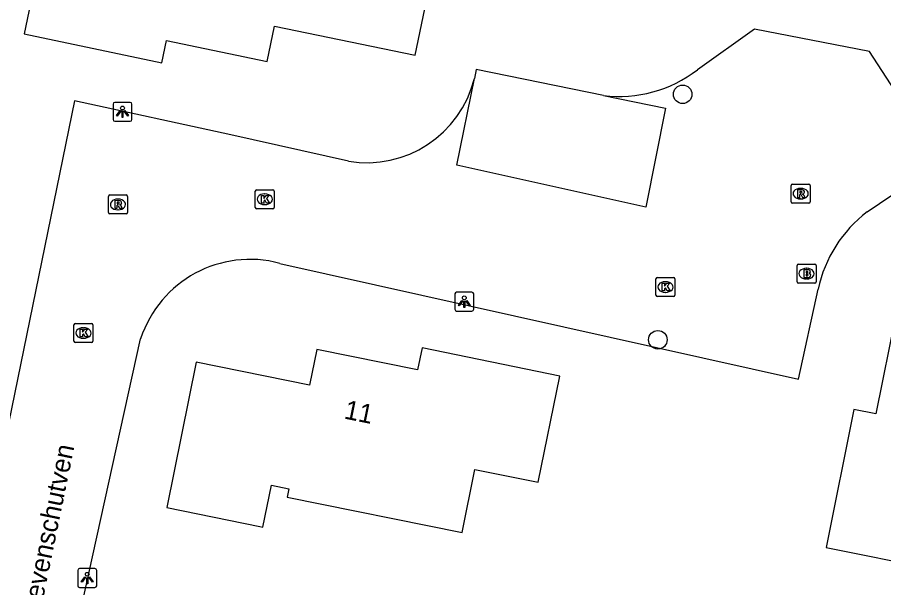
# Model space of a CAD drawing. Extents: x 163427 to 164190, y 380331 to 381641.
# Drawn here: x 163640.94 to 163686.54, y 381532.46 to 381562.48 of the extents above; entities that cross this region are included whole.
import ezdxf

# ---------------------------------------------------------------- set-up
doc = ezdxf.new("R2010")
doc.units = 0
for name, color, linetype in [('IMGEO_Boom', 7, 'Continuous'), ('IMGEO_Brandkraan', 7, 'Continuous'), ('IMGEO_Kolk', 7, 'Continuous'), ('IMGEO_Lichtpunt', 7, 'Continuous'), ('IMGEO_Openbare_ruimte_label', 7, 'Continuous'), ('IMGEO_Pand', 7, 'Continuous'), ('IMGEO_Pand_nummerreeks', 7, 'Continuous'), ('IMGEO_Parkeervlak_open', 7, 'Continuous'), ('IMGEO_Rijbaan_lokaal_open', 7, 'Continuous'), ('IMGEO_Rioolput', 7, 'Continuous')]:
    doc.layers.add(name, color=color, linetype=linetype)

msp = doc.modelspace()

# ---------------------------------------------------------------- linework, layer by layer
at = {"layer": 'IMGEO_Boom'}
for centre in [(163675.966, 381558.43), (163674.659, 381545.509)]:
    msp.add_circle(centre, 0.489, dxfattribs=at)
at = {"layer": 'IMGEO_Brandkraan'}
for p, q in [((163681.986, 381548.564), (163681.986, 381549.416)), ((163682.061, 381549.49), (163682.913, 381549.49)), ((163682.474, 381549.27), (163682.499, 381549.27)), ((163682.987, 381549.416), (163682.987, 381548.564)), ((163682.497, 381548.71), (163682.472, 381548.71)), ((163682.913, 381548.49), (163682.061, 381548.49))]:
    msp.add_line(p, q, dxfattribs=at)
for points in [[(163681.986, 381548.564), (163681.986, 381549.416)], [(163682.061, 381549.49), (163682.913, 381549.49)], [(163682.334, 381549.19), (163682.334, 381548.79), (163682.547, 381548.79)], [(163682.565, 381549.19), (163682.334, 381549.19)], [(163682.513, 381549.109), (163682.459, 381549.109), (163682.459, 381549.033)], [(163682.987, 381549.416), (163682.987, 381548.564)], [(163682.459, 381549.033), (163682.512, 381549.033)], [(163682.521, 381548.957), (163682.459, 381548.957), (163682.459, 381548.876)], [(163682.459, 381548.876), (163682.521, 381548.876)], [(163682.913, 381548.49), (163682.061, 381548.49)]]:
    msp.add_lwpolyline(points, dxfattribs=at)
for centre, radius, start, end in [((163682.063, 381549.414), 0.0765, 91.552, 178.448), ((163682.063, 381549.414), 0.0765, 91.552, 178.448), ((163682.514, 381549.071), 0.0379, 267.8285, 90.9355), ((163682.569, 381549.045), 0.145, 59.4692, 91.5367), ((163682.594, 381549.092), 0.0922, 285.5137, 58.1501), ((163682.911, 381549.414), 0.0765, 1.552, 88.448), ((163682.911, 381549.414), 0.0765, 1.552, 88.448), ((163682.522, 381548.916), 0.0404, 269.8759, 90.5077), ((163682.553, 381549.041), 0.251, 268.6676, 293.5347), ((163682.599, 381548.9), 0.105, 301.3115, 78.989), ((163682.063, 381548.566), 0.0765, 181.552, 268.448), ((163682.063, 381548.566), 0.0765, 181.552, 268.448), ((163682.911, 381548.566), 0.0765, 271.552, 358.448), ((163682.911, 381548.566), 0.0765, 271.552, 358.448)]:
    msp.add_arc(centre, radius, start, end, dxfattribs=at)
for centre, major_axis, ratio, start_param, end_param in [((163682.473, 381548.99), (-0.387, 0.002), 0.722429, 4.712389, 7.853982), ((163682.498, 381548.99), (-0.39, 0.002), 0.717154, 1.570796, 4.712389)]:
    msp.add_ellipse(centre, major_axis=major_axis, ratio=ratio, start_param=start_param, end_param=end_param, dxfattribs=at)
at = {"layer": 'IMGEO_Kolk'}
for p, q in [((163653.466, 381552.478), (163653.466, 381553.33)), ((163653.541, 381553.404), (163654.393, 381553.404)), ((163653.954, 381553.184), (163653.979, 381553.184)), ((163654.467, 381553.33), (163654.467, 381552.478)), ((163654.393, 381552.404), (163653.541, 381552.404)), ((163653.977, 381552.624), (163653.952, 381552.624)), ((163674.556, 381547.859), (163674.556, 381548.711)), ((163674.631, 381548.785), (163675.483, 381548.785)), ((163675.557, 381548.711), (163675.557, 381547.859)), ((163675.044, 381548.565), (163675.069, 381548.565)), ((163675.483, 381547.785), (163674.631, 381547.785)), ((163675.067, 381548.005), (163675.042, 381548.005)), ((163643.997, 381546.365), (163644.849, 381546.365)), ((163643.922, 381545.439), (163643.922, 381546.291)), ((163644.41, 381546.145), (163644.435, 381546.145)), ((163644.923, 381546.291), (163644.923, 381545.439)), ((163644.433, 381545.585), (163644.408, 381545.585)), ((163644.849, 381545.365), (163643.997, 381545.365))]:
    msp.add_line(p, q, dxfattribs=at)
for points in [[(163653.466, 381552.478), (163653.466, 381553.33)], [(163653.541, 381553.404), (163654.393, 381553.404)], [(163654.467, 381553.33), (163654.467, 381552.478)], [(163653.787, 381553.104), (163653.91, 381553.104), (163653.91, 381552.953), (163654.04, 381553.104), (163654.204, 381553.104), (163654.058, 381552.953), (163654.211, 381552.704), (163654.059, 381552.704), (163653.974, 381552.868), (163653.91, 381552.801), (163653.91, 381552.704), (163653.787, 381552.704), (163653.787, 381553.104)], [(163654.393, 381552.404), (163653.541, 381552.404)], [(163674.556, 381547.859), (163674.556, 381548.711)], [(163674.631, 381548.785), (163675.483, 381548.785)], [(163675.557, 381548.711), (163675.557, 381547.859)], [(163674.877, 381548.485), (163675, 381548.485), (163675, 381548.334), (163675.13, 381548.485), (163675.294, 381548.485), (163675.148, 381548.334), (163675.301, 381548.085), (163675.149, 381548.085), (163675.064, 381548.249), (163675, 381548.182), (163675, 381548.085), (163674.877, 381548.085), (163674.877, 381548.485)], [(163675.483, 381547.785), (163674.631, 381547.785)], [(163643.997, 381546.365), (163644.849, 381546.365)], [(163643.922, 381545.439), (163643.922, 381546.291)], [(163644.243, 381546.065), (163644.366, 381546.065), (163644.366, 381545.914), (163644.496, 381546.065), (163644.66, 381546.065), (163644.514, 381545.914), (163644.667, 381545.665), (163644.515, 381545.665), (163644.43, 381545.829), (163644.366, 381545.762), (163644.366, 381545.665), (163644.243, 381545.665), (163644.243, 381546.065)], [(163644.923, 381546.291), (163644.923, 381545.439)], [(163644.849, 381545.365), (163643.997, 381545.365)]]:
    msp.add_lwpolyline(points, dxfattribs=at)
for centre, start, end in [((163653.543, 381553.328), 91.552, 178.448), ((163653.543, 381553.328), 91.552, 178.448), ((163654.391, 381553.328), 1.552, 88.448), ((163654.391, 381553.328), 1.552, 88.448), ((163653.543, 381552.48), 181.552, 268.448), ((163653.543, 381552.48), 181.552, 268.448), ((163654.391, 381552.48), 271.552, 358.448), ((163654.391, 381552.48), 271.552, 358.448), ((163674.633, 381548.709), 91.552, 178.448), ((163674.633, 381548.709), 91.552, 178.448), ((163675.481, 381548.709), 1.552, 88.448), ((163675.481, 381548.709), 1.552, 88.448), ((163674.633, 381547.861), 181.552, 268.448), ((163674.633, 381547.861), 181.552, 268.448), ((163675.481, 381547.861), 271.552, 358.448), ((163675.481, 381547.861), 271.552, 358.448), ((163643.999, 381546.289), 91.552, 178.448), ((163643.999, 381546.289), 91.552, 178.448), ((163644.847, 381546.289), 1.552, 88.448), ((163644.847, 381546.289), 1.552, 88.448), ((163643.999, 381545.441), 181.552, 268.448), ((163643.999, 381545.441), 181.552, 268.448), ((163644.847, 381545.441), 271.552, 358.448), ((163644.847, 381545.441), 271.552, 358.448)]:
    msp.add_arc(centre, 0.0765, start, end, dxfattribs=at)
for centre, major_axis, ratio, start_param, end_param in [((163653.953, 381552.904), (-0.387, 0.002), 0.722429, 4.712389, 7.853982), ((163653.978, 381552.904), (-0.39, 0.002), 0.717154, 1.570796, 4.712389), ((163675.043, 381548.285), (-0.387, 0.002), 0.722429, 4.712389, 7.853982), ((163675.068, 381548.285), (-0.39, 0.002), 0.717154, 1.570796, 4.712389), ((163644.409, 381545.865), (-0.387, 0.002), 0.722429, 4.712389, 7.853982), ((163644.434, 381545.865), (-0.39, 0.002), 0.717154, 1.570796, 4.712389)]:
    msp.add_ellipse(centre, major_axis=major_axis, ratio=ratio, start_param=start_param, end_param=end_param, dxfattribs=at)
at = {"layer": 'IMGEO_Lichtpunt'}
for p, q in [((163645.98, 381557.909), (163645.98, 381557.102)), ((163645.98, 381557.909), (163645.98, 381557.102)), ((163646.882, 381558.004), (163646.074, 381558.004)), ((163646.882, 381558.004), (163646.074, 381558.004)), ((163646.976, 381557.102), (163646.976, 381557.909)), ((163646.976, 381557.102), (163646.976, 381557.909)), ((163646.074, 381557.008), (163646.882, 381557.008)), ((163646.074, 381557.008), (163646.882, 381557.008)), ((163663.972, 381547.919), (163663.972, 381547.112)), ((163663.972, 381547.919), (163663.972, 381547.112)), ((163664.874, 381548.014), (163664.066, 381548.014)), ((163664.874, 381548.014), (163664.066, 381548.014)), ((163664.968, 381547.112), (163664.968, 381547.919)), ((163664.968, 381547.112), (163664.968, 381547.919)), ((163664.066, 381547.018), (163664.874, 381547.018)), ((163664.066, 381547.018), (163664.874, 381547.018)), ((163644.124, 381533.37), (163644.124, 381532.563)), ((163644.124, 381533.37), (163644.124, 381532.563)), ((163645.026, 381533.465), (163644.218, 381533.465)), ((163645.026, 381533.465), (163644.218, 381533.465)), ((163645.12, 381532.563), (163645.12, 381533.37)), ((163645.12, 381532.563), (163645.12, 381533.37)), ((163644.218, 381532.469), (163645.026, 381532.469)), ((163644.218, 381532.469), (163645.026, 381532.469))]:
    msp.add_line(p, q, dxfattribs=at)
for points in [[(163646.354, 381557.573), (163646.393, 381557.545), (163646.205, 381557.283), (163646.167, 381557.31), (163646.354, 381557.573)], [(163646.456, 381557.525), (163646.503, 381557.525), (163646.503, 381557.203), (163646.456, 381557.203), (163646.456, 381557.525)], [(163646.566, 381557.545), (163646.604, 381557.572), (163646.791, 381557.31), (163646.752, 381557.282), (163646.566, 381557.545)], [(163664.346, 381547.583), (163664.385, 381547.555), (163664.197, 381547.293), (163664.159, 381547.32), (163664.346, 381547.583)], [(163664.448, 381547.535), (163664.495, 381547.535), (163664.495, 381547.213), (163664.448, 381547.213), (163664.448, 381547.535)], [(163664.558, 381547.555), (163664.596, 381547.582), (163664.783, 381547.32), (163664.744, 381547.292), (163664.558, 381547.555)], [(163644.498, 381533.034), (163644.537, 381533.006), (163644.349, 381532.744), (163644.311, 381532.771), (163644.498, 381533.034)], [(163644.6, 381532.986), (163644.647, 381532.986), (163644.647, 381532.664), (163644.6, 381532.664), (163644.6, 381532.986)], [(163644.71, 381533.006), (163644.748, 381533.033), (163644.935, 381532.771), (163644.896, 381532.743), (163644.71, 381533.006)]]:
    msp.add_lwpolyline(points, dxfattribs=at)
for centre in [(163646.479, 381557.707), (163664.471, 381547.717), (163644.623, 381533.168)]:
    msp.add_circle(centre, 0.0994, dxfattribs=at)
for centre, start, end in [((163646.074, 381557.909), 90, 180), ((163646.074, 381557.909), 90, 180), ((163646.882, 381557.909), 0, 90), ((163646.882, 381557.909), 0, 90), ((163646.074, 381557.102), 180, 270), ((163646.074, 381557.102), 180, 270), ((163646.882, 381557.102), 270, 0), ((163646.882, 381557.102), 270, 360), ((163664.066, 381547.919), 90, 180), ((163664.066, 381547.919), 90, 180), ((163664.874, 381547.919), 0, 90), ((163664.874, 381547.919), 0, 90), ((163664.066, 381547.112), 180, 270), ((163664.066, 381547.112), 180, 270), ((163664.874, 381547.112), 270, 0), ((163664.874, 381547.112), 270, 360), ((163644.218, 381533.37), 90, 180), ((163644.218, 381533.37), 90, 180), ((163645.026, 381533.37), 0, 90), ((163645.026, 381533.37), 0, 90), ((163644.218, 381532.563), 180, 270), ((163644.218, 381532.563), 180, 270), ((163645.026, 381532.563), 270, 0), ((163645.026, 381532.563), 270, 360)]:
    msp.add_arc(centre, 0.0946, start, end, dxfattribs=at)
at = {"layer": 'IMGEO_Pand'}
for points in [[(163648.551, 381560.092), (163648.795, 381561.256), (163654.087, 381560.149), (163654.472, 381562.021), (163661.881, 381560.489), (163662.896, 381565.385), (163663.466, 381568.137), (163656.978, 381569.475), (163656.517, 381567.252), (163655.596, 381567.443), (163655.694, 381567.913), (163646.478, 381569.826), (163645.798, 381566.491), (163642.468, 381567.186), (163642.325, 381566.5), (163641.305, 381561.605), (163648.551, 381560.092)], [(163689.113, 381533.453), (163689.782, 381536.784), (163693.115, 381536.132), (163694.969, 381545.32), (163694.509, 381545.412), (163694.694, 381546.332), (163696.896, 381545.888), (163697.719, 381549.975), (163690.093, 381551.524), (163689.083, 381546.527), (163687.206, 381546.909), (163686.14, 381541.612), (163684.976, 381541.843), (163683.515, 381534.572), (163689.113, 381533.453)], [(163664.354, 381535.361), (163665.022, 381538.677), (163668.351, 381538.013), (163669.494, 381543.595), (163662.258, 381545.085), (163662.012, 381543.927), (163656.706, 381544.997), (163656.322, 381543.117), (163650.359, 381544.336), (163648.81, 381536.673), (163653.712, 381535.685), (163653.873, 381535.653), (163654.324, 381537.85), (163655.238, 381537.662), (163655.148, 381537.225), (163664.354, 381535.361)]]:
    msp.add_lwpolyline(points, dxfattribs=at)
at = {"layer": 'IMGEO_Parkeervlak_open'}
msp.add_lwpolyline([(163671.793, 381558.373), (163665.098, 381559.741), (163665.001, 381559.265)], dxfattribs=at)
at = {"layer": 'IMGEO_Rijbaan_lokaal_open'}
for points in [[(163685.674, 381552.248), (163689.568, 381554.874), (163685.801, 381560.676), (163679.748, 381561.858), (163676.737, 381559.725)], [(163671.793, 381558.373), (163675.063, 381557.705), (163674.023, 381552.486), (163664.077, 381554.708), (163665.001, 381559.265)], [(163658.369, 381554.907), (163652.179, 381556.3), (163643.944, 381558.087), (163638.733, 381532.691), (163638.862, 381532.644)], [(163654.763, 381549.531), (163682.067, 381543.435), (163683.088, 381548.17)], [(163644.279, 381531.292), (163647.434, 381545.567)]]:
    msp.add_lwpolyline(points, dxfattribs=at)
for centre, radius, start, end in [((163672.638, 381564.999), 6.68, 262.7348, 307.8539), ((163659.336, 381560.661), 5.835, 260.4642, 346.155), ((163690.009, 381546.64), 7.088, 127.7037, 167.5359), ((163653.189, 381543.684), 6.055, 74.9307, 161.8841)]:
    msp.add_arc(centre, radius, start, end, dxfattribs=at)
at = {"layer": 'IMGEO_Rioolput'}
for p, q in [((163681.751, 381553.7), (163682.603, 381553.7)), ((163681.676, 381552.774), (163681.676, 381553.626)), ((163682.164, 381553.48), (163682.189, 381553.48)), ((163682.677, 381553.626), (163682.677, 381552.774)), ((163645.739, 381552.206), (163645.739, 381553.058)), ((163645.814, 381553.132), (163646.666, 381553.132)), ((163646.227, 381552.912), (163646.252, 381552.912)), ((163646.74, 381553.058), (163646.74, 381552.206)), ((163682.187, 381552.92), (163682.162, 381552.92)), ((163646.25, 381552.352), (163646.225, 381552.352)), ((163682.603, 381552.7), (163681.751, 381552.7)), ((163646.666, 381552.132), (163645.814, 381552.132))]:
    msp.add_line(p, q, dxfattribs=at)
for points in [[(163681.751, 381553.7), (163682.603, 381553.7)], [(163681.676, 381552.774), (163681.676, 381553.626)], [(163682.265, 381553.398), (163682.013, 381553.4), (163682.013, 381553)], [(163682.191, 381553.319), (163682.137, 381553.319), (163682.137, 381553.238)], [(163682.137, 381553.238), (163682.189, 381553.238)], [(163682.677, 381553.626), (163682.677, 381552.774)], [(163645.739, 381552.206), (163645.739, 381553.058)], [(163645.814, 381553.132), (163646.666, 381553.132)], [(163646.328, 381552.83), (163646.076, 381552.832), (163646.076, 381552.432)], [(163646.254, 381552.751), (163646.2, 381552.751), (163646.2, 381552.67)], [(163646.74, 381553.058), (163646.74, 381552.206)], [(163682.013, 381553), (163682.137, 381553), (163682.137, 381553.162), (163682.148, 381553.162)], [(163682.195, 381553.133), (163682.266, 381553), (163682.406, 381553), (163682.341, 381553.126)], [(163646.076, 381552.432), (163646.2, 381552.432), (163646.2, 381552.594), (163646.211, 381552.594)], [(163646.2, 381552.67), (163646.252, 381552.67)], [(163646.258, 381552.565), (163646.329, 381552.432), (163646.469, 381552.432), (163646.404, 381552.558)], [(163682.603, 381552.7), (163681.751, 381552.7)], [(163646.666, 381552.132), (163645.814, 381552.132)]]:
    msp.add_lwpolyline(points, dxfattribs=at)
for centre, radius, start, end in [((163681.753, 381553.624), 0.0765, 91.552, 178.448), ((163681.753, 381553.624), 0.0765, 91.552, 178.448), ((163682.601, 381553.624), 0.0765, 1.552, 88.448), ((163682.601, 381553.624), 0.0765, 1.552, 88.448), ((163682.173, 381553.427), 0.19, 274.7715, 282.9687), ((163682.197, 381553.223), 0.0964, 77.0061, 93.1865), ((163682.211, 381553.28), 0.0378, 276.6634, 79.6772), ((163682.264, 381553.288), 0.109, 350.3612, 89.416), ((163682.262, 381553.288), 0.112, 277.5842, 350.9817), ((163645.816, 381553.056), 0.0765, 91.552, 178.448), ((163645.816, 381553.056), 0.0765, 91.552, 178.448), ((163646.26, 381552.655), 0.0964, 77.0061, 93.1865), ((163646.274, 381552.712), 0.0378, 276.6634, 79.6772), ((163646.327, 381552.72), 0.109, 350.3612, 89.416), ((163646.664, 381553.056), 0.0765, 1.552, 88.448), ((163646.664, 381553.056), 0.0765, 1.552, 88.448), ((163681.753, 381552.776), 0.0765, 181.552, 268.448), ((163681.753, 381552.776), 0.0765, 181.552, 268.448), ((163682.147, 381553.109), 0.0533, 26.0293, 88.6989), ((163682.246, 381553.073), 0.108, 29.5134, 73.7905), ((163682.601, 381552.776), 0.0765, 271.552, 358.448), ((163682.601, 381552.776), 0.0765, 271.552, 358.448), ((163646.21, 381552.541), 0.0533, 26.0293, 88.6989), ((163646.236, 381552.859), 0.19, 274.7715, 282.9687), ((163646.325, 381552.72), 0.112, 277.5842, 350.9817), ((163646.309, 381552.505), 0.108, 29.5134, 73.7905), ((163645.816, 381552.208), 0.0765, 181.552, 268.448), ((163645.816, 381552.208), 0.0765, 181.552, 268.448), ((163646.664, 381552.208), 0.0765, 271.552, 358.448), ((163646.664, 381552.208), 0.0765, 271.552, 358.448)]:
    msp.add_arc(centre, radius, start, end, dxfattribs=at)
for centre, major_axis, ratio, start_param, end_param in [((163682.163, 381553.2), (-0.387, 0.002), 0.722429, 4.712389, 7.853982), ((163682.188, 381553.2), (-0.39, 0.002), 0.717154, 1.570796, 4.712389), ((163646.226, 381552.632), (-0.387, 0.002), 0.722429, 4.712389, 7.853982), ((163646.251, 381552.632), (-0.39, 0.002), 0.717154, 1.570796, 4.712389)]:
    msp.add_ellipse(centre, major_axis=major_axis, ratio=ratio, start_param=start_param, end_param=end_param, dxfattribs=at)

# ---------------------------------------------------------------- texts
at = {"layer": 'IMGEO_Openbare_ruimte_label'}
msp.add_text('Grevenschutven', height=1, rotation=78.4093, dxfattribs=at).set_placement((163641.996, 381530.358))
at = {"layer": 'IMGEO_Pand_nummerreeks'}
msp.add_text('11', height=1, rotation=348.5987, dxfattribs=at).set_placement((163658.102, 381541.37))

doc.saveas('drawing.dxf')
